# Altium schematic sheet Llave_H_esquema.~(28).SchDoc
size A4
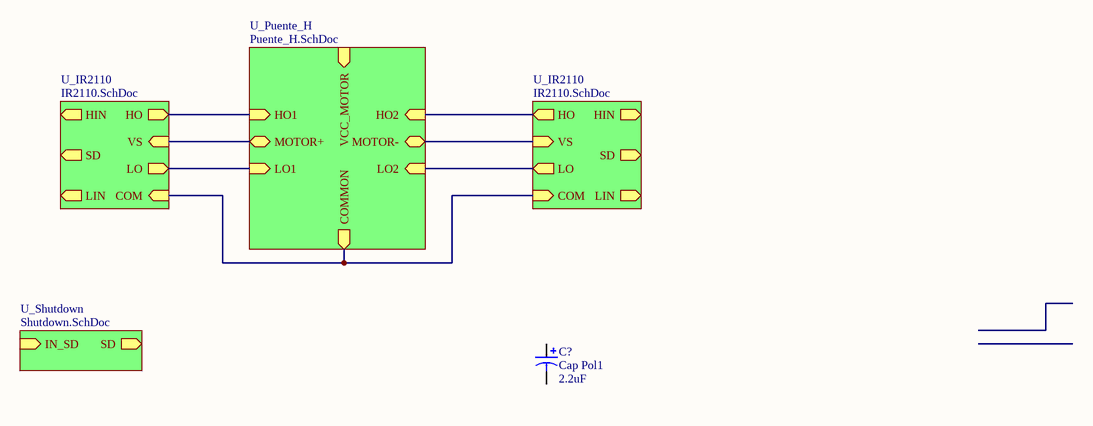
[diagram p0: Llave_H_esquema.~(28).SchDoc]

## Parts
C?  Cap Pol1  value 2.2uF  [RB7.6-15]

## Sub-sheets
U_IR2110 = IR2110.SchDoc: SD (out), HIN (out), LIN (out), HO (out), LO (out), VS (in), COM (in)
U_IR2110 = IR2110.SchDoc: SD (out), HIN (out), LIN (out), HO (out), LO (out), VS (in), COM (in)
U_Puente_H = Puente_H.SchDoc: HO1 (in), LO1 (in), HO2 (in), LO2 (in), MOTOR+ (bidir), MOTOR- (bidir), VCC_MOTOR (in), COMMON (out)
U_Shutdown = Shutdown.SchDoc: IN_SD (in), SD (out)

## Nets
(unnamed): sheet U_IR2110/HO, sheet U_Puente_H/HO1
(unnamed): sheet U_IR2110/LO, sheet U_Puente_H/LO1  [a separate net that carries the same name]
(unnamed): sheet U_IR2110/VS, sheet U_Puente_H/MOTOR+  [a separate net that carries the same name]
(unnamed): sheet U_IR2110/COM, sheet U_IR2110/COM, sheet U_Puente_H/COMMON  [a separate net that carries the same name]
(unnamed): sheet U_IR2110/HO, sheet U_Puente_H/HO2  [a separate net that carries the same name]
(unnamed): sheet U_IR2110/LO, sheet U_Puente_H/LO2  [a separate net that carries the same name]
(unnamed): sheet U_IR2110/VS, sheet U_Puente_H/MOTOR-  [a separate net that carries the same name]

Not connected (* = marked no-connect by the designer): C? 1 2

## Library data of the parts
C? = Cap Pol1: Polarized Capacitor (Radial)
